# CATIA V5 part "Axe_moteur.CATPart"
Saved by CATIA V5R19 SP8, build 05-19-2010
Part number: Axe_moteur
Revision: ANY
Definition: UNKNOWN
Nomenclature: 24
Source: Unknown
Bounding box of the stored display mesh (mm): x -9.987 to 9.987, y -9.991 to 9.991, z 0 to 67
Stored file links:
  D:\Documents\1_Travail\2- 2I2D\1 - Cours et TD\2- TD\3-TD Assemblage\Pompe AirMan\Axe_moteur.CATPart
  D:\Documents\1_Travail\3 -  Supports d'étude\Pompe_AirMan\Maquettes numériques_Pompe_AirMan\MaquettePompe_Catia\0-PompeAirman.CATProduct
  D:\Documents\1_Travail\3 -  Supports d'étude\Pompe_AirMan\Maquettes numériques_Pompe_AirMan\MaquettePompe_Catia\corps_moteur.CATPart
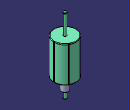
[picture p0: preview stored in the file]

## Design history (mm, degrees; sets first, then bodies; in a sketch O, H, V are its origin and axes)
Body1 "Révolution1" (main body)
  Solid1: solid without history
  Sketch1 on yz-plane, origin (0, 0, 0), H (0, 1, 0), V (0, 0, 1)
    line L1 (-3, 17) -> (0, 17)
    line L2 (0, 17) -> (0, 6)
    line L3 (0, 6) -> (-3, 6)
    line L4 (-3, 6) -> (-3, 17)
    point P3 (0, 6)
    reference intersected line E1 through (0, 17) direction (1, 0) from face of Solid1
    reference intersected line E2 through (0, 17) direction (1, 0) from face of Solid1
    distance L3 E2 = 11
    distance L4 L2 = 3
    horizontal: L1 H, L3 H
    vertical: L2 V, L4 V
    coincidence: P3 V, L1 E1
  Shaft1: profile Sketch1, axis Sketch1.L2, angle 360
  Chamfer1: length 0.5, angle 45, on edge [face of Shaft1 from Sketch1.L3 | face of Shaft1 from Sketch1.L4]
  Sketch2 on face of Solid1, origin (0, 0, 49), H (1, 0, 0), V (0, 1, 0)
    point P1 (10, 0)
    line L1 (10.5, 0.5) -> (10.5, -0.5)
    line L2 (10.5, -0.5) -> (9.5, -0.5)
    line L3 (9.5, -0.5) -> (9.5, 0.5)
    line L4 (9.5, 0.5) -> (10.5, 0.5)
    reference projected point E1 (0, 0) from axis of face of Solid1
    distance L4 L2 = 1
    distance P1 E1 = 10
    length L2 = 1
    coincidence: P1 H
    vertical: L1 V, L3 V
    horizontal: L2 H, L4 H
    equidistance: L1 L3 P1, L2 L4 P1
  Pocket1: profile Sketch2, direction (0, 0, -1), through (limit type 3)
  CircPattern1: of Pocket1, instances 6, angular step 60 {= 360.0*1 deg/CircPattern1.AngularNumber}, axis from face of Solid1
